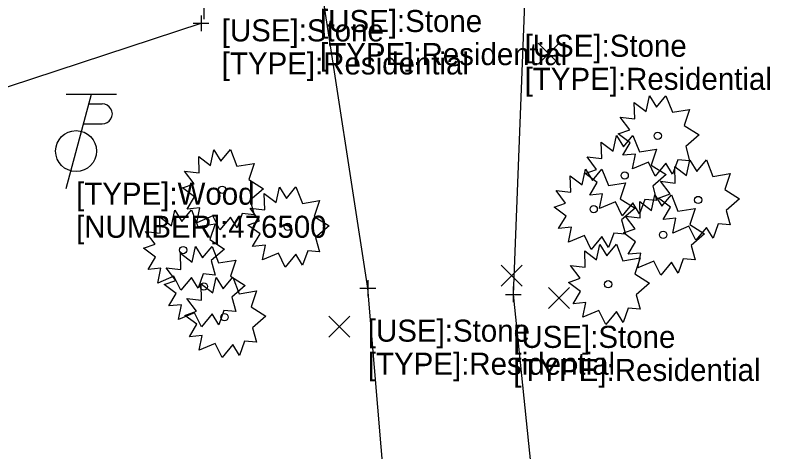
# Model space of a CAD drawing. Extents: x 1386013 to 1389776, y 604170 to 607009.
# Drawn here: x 1387085.09 to 1387133.05, y 604701.35 to 604729.07 of the extents above; entities that cross this region are included whole.
import ezdxf

# ---------------------------------------------------------------- set-up
doc = ezdxf.new("R2010")
doc.units = 0
for name, color, linetype in [('_CIVIL_CONSTRUCTION', 7, 'Continuous'), ('DV_X_Text', 7, 'Continuous'), ('PV_X_Driveway', 7, 'Continuous'), ('SV_P_Mon_Cells_Set', 7, 'Continuous'), ('SV_X_Random_Point', 7, 'Continuous'), ('SV_X_Text', 7, 'Continuous'), ('SV_X_Top_of_Bank', 7, 'Continuous')]:
    doc.layers.add(name, color=color, linetype=linetype)

msp = doc.modelspace()

# ---------------------------------------------------------------- linework, layer by layer
at = {"layer": '_CIVIL_CONSTRUCTION'}
for points in [[(1387125.838, 604723.223), (1387126.443, 604723.958), (1387126.858, 604722.905), (1387127.95, 604723.085), (1387127.611, 604722.073), (1387128.556, 604721.478), (1387127.7, 604720.743), (1387127.95, 604719.83), (1387127.196, 604719.898), (1387126.871, 604718.985), (1387126.443, 604719.676), (1387125.765, 604718.86), (1387125.336, 604719.746), (1387124.316, 604719.316), (1387124.508, 604720.258), (1387123.696, 604720.175), (1387124.17, 604720.965), (1387123.401, 604721.533), (1387124.14, 604721.796), (1387123.533, 604722.6), (1387124.465, 604722.49), (1387124.435, 604723.528), (1387125.188, 604722.96), (1387125.395, 604723.945), (1387125.838, 604723.223)], [(1387123.74, 604720.705), (1387124.345, 604721.44), (1387124.76, 604720.386), (1387125.852, 604720.566), (1387125.513, 604719.555), (1387126.458, 604718.96), (1387125.602, 604718.225), (1387125.852, 604717.311), (1387125.098, 604717.38), (1387124.773, 604716.466), (1387124.345, 604717.158), (1387123.667, 604716.341), (1387123.238, 604717.228), (1387122.218, 604716.798), (1387122.41, 604717.74), (1387121.598, 604717.656), (1387122.072, 604718.446), (1387121.303, 604719.015), (1387122.042, 604719.278), (1387121.435, 604720.081), (1387122.367, 604719.971), (1387122.337, 604721.01), (1387123.09, 604720.441), (1387123.297, 604721.426), (1387123.74, 604720.705)], [(1387098.163, 604719.8), (1387098.768, 604720.535), (1387099.183, 604719.482), (1387100.275, 604719.662), (1387099.936, 604718.65), (1387100.881, 604718.055), (1387100.025, 604717.32), (1387100.275, 604716.407), (1387099.521, 604716.475), (1387099.196, 604715.562), (1387098.768, 604716.254), (1387098.09, 604715.437), (1387097.661, 604716.324), (1387096.641, 604715.894), (1387096.833, 604716.835), (1387096.021, 604716.752), (1387096.495, 604717.542), (1387095.726, 604718.11), (1387096.465, 604718.374), (1387095.858, 604719.177), (1387096.79, 604719.067), (1387096.76, 604720.105), (1387097.513, 604719.537), (1387097.72, 604720.522), (1387098.163, 604719.8)], [(1387128.408, 604719.15), (1387129.013, 604719.885), (1387129.428, 604718.832), (1387130.52, 604719.012), (1387130.181, 604718), (1387131.126, 604717.405), (1387130.27, 604716.67), (1387130.52, 604715.757), (1387129.766, 604715.825), (1387129.441, 604714.912), (1387129.013, 604715.603), (1387128.335, 604714.787), (1387127.906, 604715.673), (1387126.886, 604715.243), (1387127.078, 604716.185), (1387126.266, 604716.102), (1387126.74, 604716.892), (1387125.971, 604717.46), (1387126.71, 604717.723), (1387126.103, 604718.527), (1387127.035, 604718.417), (1387127.005, 604719.455), (1387127.758, 604718.887), (1387127.965, 604719.872), (1387128.408, 604719.15)], [(1387121.768, 604718.569), (1387122.373, 604719.304), (1387122.788, 604718.25), (1387123.88, 604718.43), (1387123.541, 604717.419), (1387124.486, 604716.824), (1387123.63, 604716.089), (1387123.88, 604715.175), (1387123.126, 604715.244), (1387122.801, 604714.33), (1387122.373, 604715.022), (1387121.695, 604714.205), (1387121.266, 604715.092), (1387120.246, 604714.662), (1387120.438, 604715.604), (1387119.626, 604715.52), (1387120.1, 604716.31), (1387119.331, 604716.879), (1387120.07, 604717.142), (1387119.463, 604717.945), (1387120.395, 604717.835), (1387120.365, 604718.874), (1387121.118, 604718.305), (1387121.325, 604719.29), (1387121.768, 604718.569)], [(1387102.324, 604717.441), (1387102.929, 604718.176), (1387103.344, 604717.123), (1387104.436, 604717.303), (1387104.097, 604716.291), (1387105.042, 604715.696), (1387104.186, 604714.961), (1387104.436, 604714.048), (1387103.682, 604714.116), (1387103.357, 604713.203), (1387102.929, 604713.894), (1387102.251, 604713.078), (1387101.822, 604713.964), (1387100.802, 604713.534), (1387100.994, 604714.476), (1387100.182, 604714.393), (1387100.656, 604715.183), (1387099.887, 604715.751), (1387100.626, 604716.014), (1387100.019, 604716.818), (1387100.951, 604716.708), (1387100.921, 604717.746), (1387101.674, 604717.178), (1387101.881, 604718.163), (1387102.324, 604717.441)], [(1387126.185, 604716.939), (1387126.79, 604717.674), (1387127.205, 604716.621), (1387128.297, 604716.801), (1387127.958, 604715.789), (1387128.903, 604715.194), (1387128.047, 604714.459), (1387128.297, 604713.546), (1387127.543, 604713.614), (1387127.218, 604712.701), (1387126.79, 604713.392), (1387126.112, 604712.576), (1387125.683, 604713.462), (1387124.663, 604713.032), (1387124.855, 604713.974), (1387124.043, 604713.891), (1387124.517, 604714.681), (1387123.748, 604715.249), (1387124.487, 604715.512), (1387123.88, 604716.316), (1387124.812, 604716.206), (1387124.782, 604717.244), (1387125.535, 604716.676), (1387125.742, 604717.661), (1387126.185, 604716.939)], [(1387095.684, 604715.972), (1387096.289, 604716.707), (1387096.704, 604715.653), (1387097.796, 604715.833), (1387097.457, 604714.822), (1387098.402, 604714.227), (1387097.546, 604713.492), (1387097.796, 604712.578), (1387097.042, 604712.647), (1387096.717, 604711.733), (1387096.289, 604712.425), (1387095.611, 604711.608), (1387095.182, 604712.495), (1387094.162, 604712.065), (1387094.354, 604713.007), (1387093.542, 604712.923), (1387094.016, 604713.713), (1387093.247, 604714.282), (1387093.986, 604714.545), (1387093.379, 604715.348), (1387094.311, 604715.238), (1387094.281, 604716.277), (1387095.034, 604715.708), (1387095.241, 604716.693), (1387095.684, 604715.972)], [(1387096.996, 604713.66), (1387097.601, 604714.395), (1387098.016, 604713.341), (1387099.108, 604713.521), (1387098.769, 604712.51), (1387099.714, 604711.915), (1387098.858, 604711.18), (1387099.108, 604710.266), (1387098.354, 604710.335), (1387098.029, 604709.421), (1387097.601, 604710.113), (1387096.923, 604709.296), (1387096.494, 604710.183), (1387095.474, 604709.753), (1387095.666, 604710.695), (1387094.854, 604710.611), (1387095.328, 604711.401), (1387094.559, 604711.97), (1387095.298, 604712.233), (1387094.691, 604713.036), (1387095.623, 604712.926), (1387095.593, 604713.965), (1387096.346, 604713.396), (1387096.553, 604714.381), (1387096.996, 604713.66)], [(1387122.69, 604713.799), (1387123.295, 604714.534), (1387123.71, 604713.481), (1387124.802, 604713.661), (1387124.463, 604712.649), (1387125.408, 604712.054), (1387124.552, 604711.319), (1387124.802, 604710.406), (1387124.048, 604710.474), (1387123.723, 604709.561), (1387123.295, 604710.252), (1387122.617, 604709.436), (1387122.188, 604710.322), (1387121.168, 604709.892), (1387121.36, 604710.834), (1387120.548, 604710.751), (1387121.022, 604711.541), (1387120.253, 604712.109), (1387120.992, 604712.372), (1387120.385, 604713.176), (1387121.317, 604713.066), (1387121.287, 604714.104), (1387122.04, 604713.536), (1387122.247, 604714.521), (1387122.69, 604713.799)], [(1387098.309, 604711.708), (1387098.914, 604712.443), (1387099.329, 604711.39), (1387100.421, 604711.57), (1387100.082, 604710.558), (1387101.027, 604709.963), (1387100.171, 604709.228), (1387100.421, 604708.315), (1387099.667, 604708.383), (1387099.342, 604707.47), (1387098.914, 604708.162), (1387098.236, 604707.345), (1387097.807, 604708.232), (1387096.787, 604707.802), (1387096.979, 604708.743), (1387096.167, 604708.66), (1387096.641, 604709.45), (1387095.872, 604710.018), (1387096.611, 604710.282), (1387096.004, 604711.085), (1387096.936, 604710.975), (1387096.906, 604712.013), (1387097.659, 604711.445), (1387097.866, 604712.43), (1387098.309, 604711.708)]]:
    msp.add_lwpolyline(points, dxfattribs=at)
for centre in [(1387125.922, 604721.414), (1387123.824, 604718.895), (1387098.247, 604717.991), (1387128.492, 604717.341), (1387121.852, 604716.759), (1387102.408, 604715.631), (1387126.269, 604715.129), (1387095.768, 604714.162), (1387097.08, 604711.85), (1387122.774, 604711.989), (1387098.393, 604709.899)]:
    msp.add_circle(centre, 0.23, dxfattribs=at)
at = {"layer": 'DV_X_Text'}
for p, q in [((1387097.079, 604729.809), (1387097.079, 604728.809)), ((1387096.903, 604729.058), (1387096.903, 604728.058)), ((1387096.403, 604728.558), (1387097.403, 604728.558)), ((1387096.903, 604728.558), (1387096.903, 604728.558)), ((1387107.501, 604712.245), (1387107.501, 604711.245)), ((1387107.001, 604711.745), (1387108.001, 604711.745)), ((1387107.501, 604711.745), (1387107.501, 604711.745)), ((1387116.741, 604711.851), (1387116.741, 604710.851)), ((1387116.241, 604711.351), (1387117.241, 604711.351)), ((1387116.741, 604711.351), (1387116.741, 604711.351))]:
    msp.add_line(p, q, dxfattribs=at)
at = {"layer": 'PV_X_Driveway'}
msp.add_lwpolyline([(1387118.134, 604745.046), (1387117.463, 604729.829), (1387116.741, 604711.351), (1387120.406, 604675.776), (1387122.468, 604635.8), (1387113.896, 604634.772), (1387110.678, 604673.979), (1387107.501, 604711.745), (1387104.464, 604731.399), (1387098.218, 604730.805), (1387096.815, 604742.493)], dxfattribs=at)
at = {"layer": 'SV_P_Mon_Cells_Set'}
for p, q in [((1387089.926, 604724.041), (1387088.32, 604718.041)), ((1387091.526, 604724.041), (1387088.326, 604724.041)), ((1387089.766, 604723.441), (1387090.616, 604723.441)), ((1387089.425, 604722.166), (1387090.616, 604722.166))]:
    msp.add_line(p, q, dxfattribs=at)
msp.add_circle((1387088.963, 604720.441), 1.3, dxfattribs=at)
msp.add_arc((1387090.629, 604722.804), 0.638, 268.8767, 91.1233, dxfattribs=at)
at = {"layer": 'SV_X_Random_Point'}
for p, q in [((1387118.333, 604725.952), (1387119.667, 604727.287)), ((1387118.333, 604727.287), (1387119.667, 604725.952)), ((1387115.969, 604711.869), (1387117.303, 604713.204)), ((1387115.969, 604713.204), (1387117.303, 604711.869)), ((1387118.975, 604710.454), (1387120.309, 604711.789)), ((1387118.975, 604711.789), (1387120.309, 604710.454)), ((1387105.02, 604708.623), (1387106.354, 604709.958)), ((1387105.02, 604709.958), (1387106.354, 604708.623))]:
    msp.add_line(p, q, dxfattribs=at)
at = {"layer": 'SV_X_Top_of_Bank'}
msp.add_lwpolyline([(1386991.064, 604711.971), (1387009.58, 604713.197), (1387021.12, 604717.384), (1387040.651, 604719.25), (1387081.612, 604723.554), (1387096.903, 604728.558)], dxfattribs=at)

# ---------------------------------------------------------------- texts
at = {"layer": 'SV_X_Text'}
for s, p in [('[USE]:Stone', (1387104.464, 604727.999)), ('[USE]:Stone', (1387098.218, 604727.405)), ('[USE]:Stone', (1387117.463, 604726.429)), ('[TYPE]:Residential', (1387104.464, 604725.899)), ('[TYPE]:Residential', (1387098.218, 604725.305)), ('[TYPE]:Residential', (1387117.463, 604724.329)), ('[TYPE]:Wood', (1387088.963, 604717.041)), ('[NUMBER]:476500', (1387088.963, 604714.941)), ('[USE]:Stone', (1387107.501, 604708.345)), ('[USE]:Stone', (1387116.741, 604707.951)), ('[TYPE]:Residential', (1387107.501, 604706.245)), ('[TYPE]:Residential', (1387116.741, 604705.851))]:
    msp.add_text(s, height=1.4, dxfattribs=at).set_placement(p)

doc.saveas('drawing.dxf')
